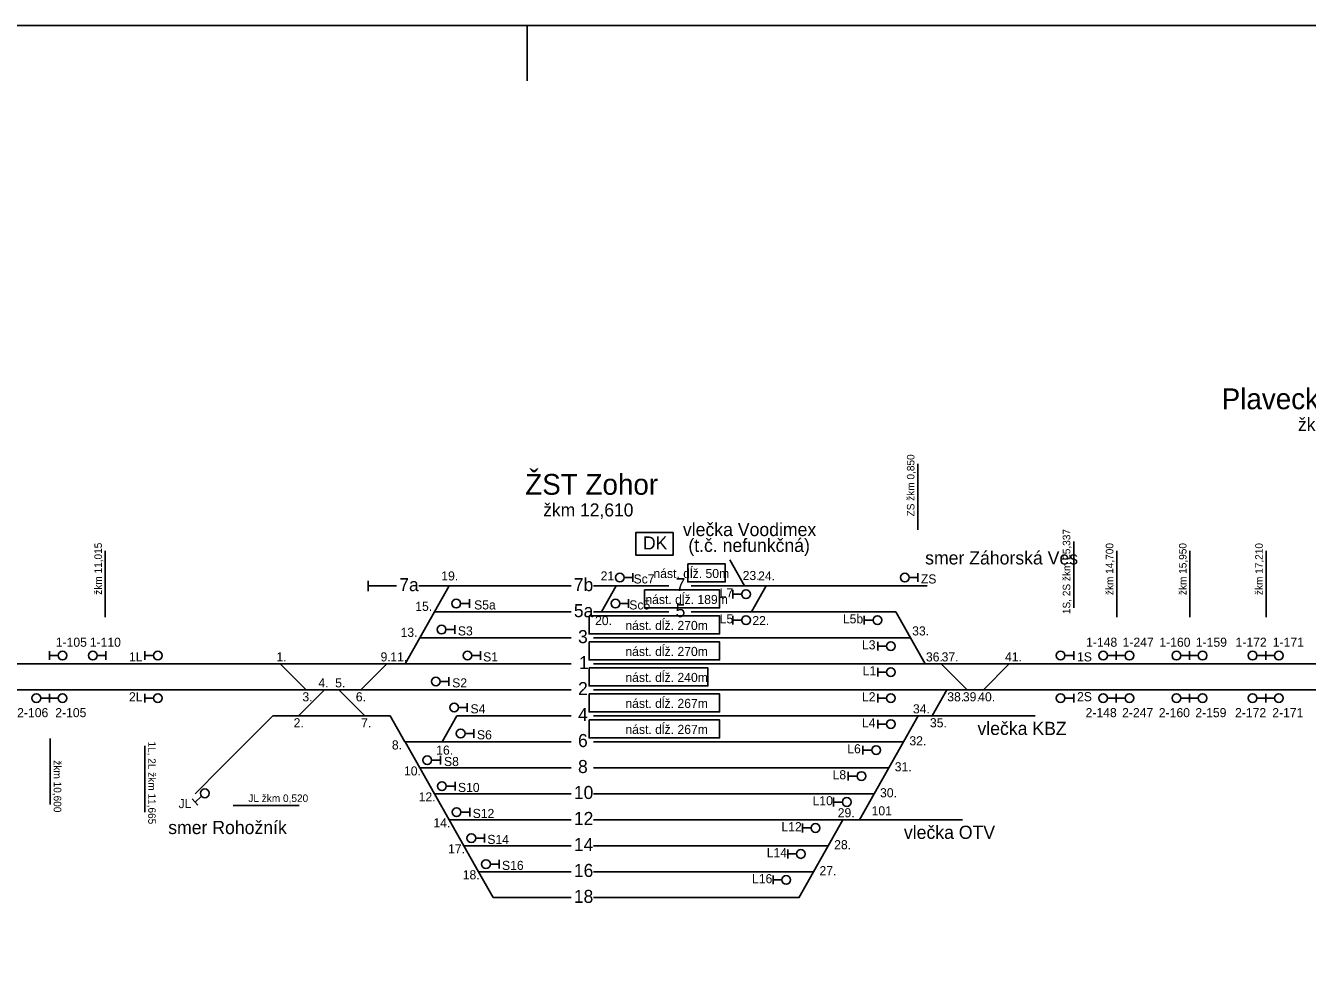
# Model space of a CAD drawing. Extents: x -119 to 851, y -238 to 59.
# Drawn here: x 52.5 to 151.1, y -14.4 to 59 of the extents above; entities that cross this region are included whole.
import ezdxf

# ---------------------------------------------------------------- set-up
doc = ezdxf.new("R2010")
doc.units = 0
for name, color, linetype in [('budova', 7, 'Continuous'), ('Level 2', 7, 'Continuous'), ('nastupistia', 7, 'Continuous'), ('netlač', 7, 'Continuous'), ('popisky navestidla', 7, 'Continuous'), ('popisky stanic a zastavok', 7, 'Continuous'), ('PU_navestidla', 7, 'Continuous'), ('PU_oznacenie navestidiel', 7, 'Continuous'), ('PU_stan_kolaje', 7, 'Continuous'), ('PU_vlecky', 7, 'Continuous')]:
    doc.layers.add(name, color=color, linetype=linetype)

msp = doc.modelspace()

# ---------------------------------------------------------------- linework, layer by layer
at = {"layer": 'budova'}
msp.add_lwpolyline([(102.283, 19.997), (99.416, 19.997), (99.416, 18.249), (102.283, 18.249)], close=True, dxfattribs=at)
at = {"layer": 'Level 2'}
for p, q in [((78.82, 16.285), (78.82, 15.485)), ((64.994, 9.889), (61.622, 9.889)), ((83.291, 9.889), (64.994, 9.889)), ((94.434, 9.889), (83.291, 9.889)), ((109.088, 9.889), (96.158, 9.889)), ((133.114, 9.889), (109.088, 9.889)), ((84.291, 7.89), (61.622, 7.89)), ((94.434, 7.89), (84.291, 7.89)), ((107.888, 7.89), (96.158, 7.89)), ((124.086, 7.89), (107.888, 7.89)), ((133.114, 7.89), (124.086, 7.89))]:
    msp.add_line(p, q, dxfattribs=at)
at = {"layer": 'nastupistia'}
for points in [[(103.408, 17.573), (106.293, 17.573), (106.293, 16.188), (103.408, 16.188)], [(100.081, 15.574), (105.856, 15.574), (105.856, 14.189), (100.081, 14.189)], [(95.817, 13.575), (105.856, 13.575), (105.856, 12.19), (95.817, 12.19)], [(95.817, 11.576), (105.856, 11.576), (105.856, 10.191), (95.817, 10.191)], [(95.817, 9.577), (104.958, 9.577), (104.958, 8.192), (95.817, 8.192)], [(95.817, 7.578), (105.856, 7.578), (105.856, 6.193), (95.817, 6.193)], [(95.817, 5.579), (105.856, 5.579), (105.856, 4.194), (95.817, 4.194)]]:
    msp.add_lwpolyline(points, close=True, dxfattribs=at)
at = {"layer": 'netlač'}
for p, q in [((80.999, 15.886), (78.82, 15.885)), ((85.049, 15.886), (82.722, 15.886)), ((94.434, 15.886), (85.049, 15.886)), ((96.158, 15.886), (97.91, 15.886)), ((97.91, 15.886), (100.695, 15.886)), ((100.695, 15.886), (101.945, 15.886)), ((103.669, 15.886), (109.436, 15.886)), ((109.436, 15.886), (121.834, 15.886)), ((94.434, 13.887), (83.918, 13.887)), ((96.158, 13.887), (101.945, 13.887)), ((103.669, 13.887), (119.418, 13.887)), ((94.434, 11.888), (82.788, 11.888)), ((96.158, 11.888), (120.548, 11.888)), ((12.578, 9.889), (61.622, 9.889)), ((133.114, 9.889), (179.871, 9.889)), ((12.578, 7.89), (61.622, 7.89)), ((133.114, 7.89), (179.871, 7.89)), ((80.5, 5.891), (71.486, 5.891)), ((85.642, 5.891), (94.434, 5.891)), ((122.208, 5.891), (96.158, 5.891)), ((122.208, 5.891), (130.153, 5.891)), ((81.63, 3.892), (94.434, 3.892)), ((96.158, 3.892), (120.01, 3.892)), ((82.785, 1.893), (94.434, 1.893)), ((96.158, 1.893), (118.88, 1.893)), ((83.915, -0.105), (94.434, -0.105)), ((96.158, -0.105), (117.75, -0.105)), ((85.045, -2.104), (94.434, -2.104)), ((96.158, -2.104), (116.62, -2.104)), ((116.62, -2.104), (124.565, -2.104)), ((86.175, -4.102), (94.434, -4.102)), ((96.158, -4.102), (114.222, -4.102)), ((87.305, -6.101), (94.434, -6.101)), ((96.158, -6.101), (113.092, -6.101)), ((88.435, -8.099), (94.434, -8.099)), ((96.158, -8.099), (111.962, -8.099))]:
    msp.add_line(p, q, dxfattribs=at)
at = {"layer": 'popisky navestidla'}
for p, q in [((91.049, 58.992), (91.049, 54.755)), ((121.119, 20.199), (121.119, 25.29)), ((133.114, 14.202), (133.114, 19.293)), ((58.586, 13.488), (58.586, 18.579)), ((136.424, 13.488), (136.424, 18.579)), ((142.059, 13.488), (142.059, 18.579)), ((147.924, 13.488), (147.924, 18.579)), ((54.352, 4.154), (54.352, -0.937)), ((61.622, 3.578), (61.622, -1.513)), ((68.417, -1.003), (73.508, -1.003))]:
    msp.add_line(p, q, dxfattribs=at)
msp.add_lwpolyline([(-118.951, -238.008), (851.049, -238.008), (851.049, 58.992), (-118.951, 58.992)], close=True, dxfattribs=at)
at = {"layer": 'PU_navestidla'}
for p, q in [((99.188, 16.859), (99.188, 16.187)), ((121.119, 16.859), (121.119, 16.187)), ((99.188, 16.522), (98.516, 16.522)), ((121.119, 16.522), (120.447, 16.522)), ((86.603, 14.86), (86.603, 14.188)), ((98.86, 14.86), (98.86, 14.188)), ((106.887, 14.914), (106.887, 15.586)), ((106.887, 15.251), (107.559, 15.251)), ((86.603, 14.523), (85.931, 14.523)), ((98.86, 14.523), (98.188, 14.523)), ((85.473, 12.861), (85.473, 12.189)), ((106.887, 12.915), (106.887, 13.587)), ((106.887, 13.252), (107.559, 13.252)), ((116.997, 12.915), (116.997, 13.587)), ((116.997, 13.252), (117.669, 13.252)), ((85.473, 12.524), (84.801, 12.524)), ((54.286, 10.86), (54.286, 10.188)), ((58.627, 10.185), (58.627, 10.857)), ((61.622, 10.861), (61.622, 10.189)), ((87.471, 10.862), (87.471, 10.19)), ((118.028, 10.916), (118.028, 11.588)), ((118.028, 11.253), (118.7, 11.253)), ((133.114, 10.862), (133.114, 10.19)), ((136.391, 10.86), (136.391, 10.188)), ((136.391, 10.86), (136.391, 10.188)), ((142.025, 10.86), (142.025, 10.188)), ((142.025, 10.86), (142.025, 10.188)), ((147.89, 10.86), (147.89, 10.188)), ((147.89, 10.86), (147.89, 10.188)), ((54.286, 10.522), (54.958, 10.522)), ((58.627, 10.522), (57.955, 10.522)), ((61.622, 10.523), (62.294, 10.523)), ((87.471, 10.525), (86.799, 10.525)), ((133.114, 10.525), (132.442, 10.525)), ((136.391, 10.522), (135.719, 10.522)), ((136.391, 10.522), (137.063, 10.522)), ((142.025, 10.522), (141.353, 10.522)), ((142.025, 10.522), (142.697, 10.522)), ((147.89, 10.522), (147.218, 10.522)), ((147.89, 10.522), (148.562, 10.522)), ((118.028, 8.917), (118.028, 9.589)), ((118.028, 9.254), (118.7, 9.254)), ((85.034, 8.526), (84.362, 8.526)), ((85.034, 8.863), (85.034, 8.191)), ((54.286, 7.251), (53.614, 7.251)), ((54.286, 6.917), (54.286, 7.589)), ((54.286, 7.589), (54.286, 6.917)), ((54.286, 7.254), (54.958, 7.254)), ((61.622, 6.918), (61.622, 7.59)), ((61.622, 7.255), (62.294, 7.255)), ((118.028, 6.918), (118.028, 7.59)), ((118.028, 7.255), (118.7, 7.255)), ((133.114, 7.255), (132.442, 7.255)), ((133.114, 6.918), (133.114, 7.59)), ((136.391, 7.254), (135.719, 7.254)), ((136.391, 6.917), (136.391, 7.589)), ((136.391, 6.917), (136.391, 7.589)), ((136.391, 7.254), (137.063, 7.254)), ((142.025, 7.254), (141.353, 7.254)), ((142.025, 6.917), (142.025, 7.589)), ((142.025, 6.917), (142.025, 7.589)), ((142.025, 7.254), (142.697, 7.254)), ((147.89, 7.254), (147.218, 7.254)), ((147.89, 6.917), (147.89, 7.589)), ((147.89, 6.917), (147.89, 7.589)), ((147.89, 7.254), (148.562, 7.254)), ((86.446, 6.527), (85.774, 6.527)), ((86.446, 6.864), (86.446, 6.192)), ((118.028, 4.919), (118.028, 5.591)), ((118.028, 5.256), (118.7, 5.256)), ((86.942, 4.528), (86.27, 4.528)), ((86.942, 4.865), (86.942, 4.193)), ((116.897, 2.92), (116.897, 3.592)), ((116.897, 3.257), (117.569, 3.257)), ((84.371, 2.474), (83.699, 2.474)), ((84.371, 2.811), (84.371, 2.139)), ((115.767, 0.921), (115.767, 1.593)), ((115.767, 1.258), (116.439, 1.258)), ((85.501, 0.475), (84.829, 0.475)), ((85.501, 0.812), (85.501, 0.141)), ((65.714, -0.993), (65.267, -0.491)), ((65.489, -0.741), (65.991, -0.294)), ((114.637, -1.078), (114.637, -0.406)), ((114.637, -0.741), (115.309, -0.741)), ((86.631, -1.523), (85.959, -1.523)), ((86.631, -1.186), (86.631, -1.858)), ((112.238, -3.077), (112.238, -2.405)), ((112.238, -2.74), (112.91, -2.74)), ((87.761, -3.522), (87.089, -3.522)), ((87.761, -3.184), (87.761, -3.856)), ((111.108, -5.075), (111.108, -4.403)), ((111.108, -4.738), (111.78, -4.738)), ((88.891, -5.52), (88.219, -5.52)), ((88.891, -5.183), (88.891, -5.855)), ((109.978, -7.075), (109.978, -6.403)), ((109.978, -6.738), (110.65, -6.738))]:
    msp.add_line(p, q, dxfattribs=at)
for centre in [(98.18, 16.523), (120.111, 16.523), (85.595, 14.524), (97.852, 14.524), (107.895, 15.25), (84.465, 12.525), (107.895, 13.251), (118.005, 13.251), (55.294, 10.524), (57.619, 10.521), (62.63, 10.525), (86.463, 10.526), (119.036, 11.252), (132.106, 10.526), (135.383, 10.524), (137.399, 10.524), (141.017, 10.524), (143.033, 10.524), (146.882, 10.524), (148.898, 10.524), (119.036, 9.253), (84.026, 8.527), (53.278, 7.253), (55.294, 7.253), (62.63, 7.254), (119.036, 7.254), (132.106, 7.254), (135.383, 7.253), (137.399, 7.253), (141.017, 7.253), (143.033, 7.253), (146.882, 7.253), (148.898, 7.253), (85.438, 6.528), (119.036, 5.255), (85.934, 4.529), (117.905, 3.256), (83.363, 2.475), (116.775, 1.257), (66.243, -0.072), (84.493, 0.477), (115.645, -0.742), (85.623, -1.522), (113.246, -2.741), (86.753, -3.52), (112.116, -4.739), (87.883, -5.519), (110.986, -6.739)]:
    msp.add_circle(centre, 0.336, dxfattribs=at)
at = {"layer": 'PU_stan_kolaje'}
for points in [[(107.766, 15.886), (106.637, 17.884)], [(85.049, 15.886), (83.918, 13.887)], [(97.91, 15.886), (96.779, 13.887)], [(109.436, 15.886), (108.305, 13.887)], [(83.918, 13.887), (82.788, 11.888)], [(120.548, 11.888), (119.418, 13.887)], [(82.788, 11.888), (81.658, 9.889)], [(121.678, 9.889), (120.548, 11.888)], [(74.042, 7.89), (72.043, 9.889)], [(78.247, 7.89), (80.246, 9.889)], [(124.916, 7.89), (122.917, 9.889)], [(126.16, 7.89), (128.159, 9.889)], [(73.461, 5.891), (75.46, 7.89)], [(78.564, 5.891), (76.565, 7.89)], [(123.339, 7.89), (122.208, 5.891)], [(69.487, 3.892), (71.486, 5.891)], [(81.63, 3.892), (80.5, 5.89)], [(85.642, 5.891), (84.512, 3.892)], [(121.14, 5.891), (120.01, 3.892)], [(67.488, 1.893), (69.487, 3.892)], [(82.785, 1.893), (81.655, 3.892)], [(120.01, 3.892), (118.88, 1.893)], [(65.489, -0.106), (67.488, 1.893)], [(83.915, -0.105), (82.785, 1.893)], [(118.88, 1.893), (117.749, -0.106)], [(85.045, -2.104), (83.915, -0.105)], [(117.749, -0.106), (116.619, -2.105)], [(86.175, -4.102), (85.045, -2.104)], [(115.352, -2.104), (114.221, -4.103)], [(87.305, -6.101), (86.175, -4.102)], [(114.221, -4.103), (113.091, -6.102)], [(88.435, -8.099), (87.305, -6.101)], [(113.091, -6.102), (111.961, -8.101)]]:
    msp.add_lwpolyline(points, dxfattribs=at)

# ---------------------------------------------------------------- texts
at = {"layer": 'budova'}
msp.add_text('DK', height=1.0044, dxfattribs=at).set_placement((99.971, 18.688))
at = {"layer": 'nastupistia'}
for s, p in [('nást. dĺž. 50m', (100.771, 16.49)), ('nást. dĺž. 189m', (100.148, 14.491)), ('nást. dĺž. 270m', (98.611, 12.492)), ('nást. dĺž. 270m', (98.611, 10.493)), ('nást. dĺž. 240m', (98.611, 8.494)), ('nást. dĺž. 267m', (98.611, 6.495)), ('nást. dĺž. 267m', (98.611, 4.496))]:
    msp.add_text(s, height=0.7, dxfattribs=at).set_placement(p)
at = {"layer": 'popisky navestidla'}
for s, height, rotation, p in [('ZS žkm 0,850 ', 0.57931, 90, (120.856, 21.228)), ('1S, 2S žkm 25,337', 0.57931, 90, (132.851, 13.716)), ('žkm 11,015', 0.5793, 90, (58.323, 15.205)), ('žkm 14,700', 0.5793, 90, (136.161, 15.18)), ('žkm 15,950', 0.5793, 90, (141.796, 15.18)), ('žkm 17,210', 0.5793, 90, (147.661, 15.18)), ('1L, 2L žkm 11,665', 0.57931, 270, (61.885, 3.921)), ('žkm 10,600', 0.5793, 270, (54.615, 2.462)), ('JL žkm 0,520', 0.57931, 360, (69.592, -0.74))]:
    msp.add_text(s, height=height, rotation=rotation, dxfattribs=at).set_placement(p)
at = {"layer": 'popisky stanic a zastavok'}
for s, height, p in [('Plavecký Štvrtok zast.', 1.6, (144.502, 29.479)), ('žkm 17,993', 1.0044, (150.379, 27.811)), ('ŽST Zohor', 1.6, (90.904, 22.898)), ('žkm 12,610', 1.0044, (92.285, 21.23))]:
    msp.add_text(s, height=height, dxfattribs=at).set_placement(p)
at = {"layer": 'PU_oznacenie navestidiel'}
for s, p in [('19.', (84.445, 16.305)), ('21.', (96.706, 16.303)), ('Sc7', (99.24, 16.073)), ('23.', (107.636, 16.336)), ('24.', (108.828, 16.303)), ('ZS', (121.352, 16.073)), ('L7', (105.869, 15)), ('15.', (82.44, 13.963)), ('S5a', (86.967, 14.074)), ('Sc5', (98.91, 14.074)), ('20.', (96.277, 12.868)), ('L5', (105.866, 13.001)), ('22.', (108.382, 12.868)), ('L5b', (115.348, 13.001)), ('1-105', (54.773, 11.203)), ('1-110', (57.391, 11.203)), ('13.', (81.309, 11.964)), ('S3', (85.72, 12.075)), ('33.', (120.683, 12.074)), ('1-148', (134.068, 11.203)), ('1-247', (136.879, 11.203)), ('1-160', (139.705, 11.203)), ('1-159', (142.513, 11.203)), ('1-172', (145.571, 11.203)), ('1-171', (148.434, 11.203)), ('L3', (116.818, 11.002)), ('1L', (60.409, 10.075)), ('1.', (71.754, 10.075)), ('9.', (79.77, 10.075)), ('11.', (80.516, 10.075)), ('S1', (87.663, 10.076)), ('36.', (121.743, 10.075)), ('37.', (122.949, 10.075)), ('41.', (127.822, 10.075)), ('1S', (133.37, 10.076)), ('L1', (116.873, 9.003)), ('4.', (74.983, 8.076)), ('5.', (76.276, 8.076)), ('S2', (85.283, 8.077)), ('2L', (60.409, 7.004)), ('3.', (73.753, 7.004)), ('6.', (77.864, 7.004)), ('L2', (116.82, 7.004)), ('38.', (123.385, 7.004)), ('39.', (124.583, 7.004)), ('40.', (125.765, 7.004)), ('2S', (133.37, 7.015)), ('2-106', (51.802, 5.786)), ('2-105', (54.734, 5.786)), ('S4', (86.693, 6.078)), ('34.', (120.742, 6.077)), ('2-148', (134.03, 5.786)), ('2-247', (136.841, 5.786)), ('2-160', (139.666, 5.786)), ('2-159', (142.474, 5.786)), ('2-172', (145.532, 5.786)), ('2-171', (148.395, 5.786)), ('2.', (73.078, 5.005)), ('7.', (78.275, 5.005)), ('L4', (116.819, 5.005)), ('35.', (122.05, 5.005)), ('8.', (80.641, 3.3)), ('S6', (87.189, 4.079)), ('32.', (120.469, 3.618)), ('16.', (84.052, 2.902)), ('L6', (115.688, 3.006)), ('10.', (81.573, 1.302)), ('S8', (84.651, 2.025)), ('31.', (119.339, 1.619)), ('L8', (114.557, 1.007)), ('12.', (82.703, -0.697)), ('S10', (85.726, 0.027)), ('30.', (118.209, -0.38)), ('JL', (64.221, -1.212)), ('L10', (113.016, -0.992)), ('S12', (86.858, -1.972)), ('29.', (114.953, -1.918)), ('101', (117.56, -1.768)), ('14.', (83.833, -2.695)), ('L12', (110.62, -2.991)), ('S14', (87.986, -3.97)), ('28.', (114.68, -4.377)), ('17.', (84.963, -4.694)), ('L14', (109.488, -4.989)), ('S16', (89.115, -5.969)), ('27.', (113.55, -6.376)), ('18.', (86.093, -6.692)), ('L16', (108.357, -6.989))]:
    msp.add_text(s, height=0.7, dxfattribs=at).set_placement(p)
at = {"layer": 'PU_stan_kolaje'}
for s, height, p in [('7a', 1.0044, (81.209, 15.481)), ('7b', 1.0044, (94.644, 15.481)), ('7', 1.004, (102.478, 15.481)), ('5a', 1.0044, (94.645, 13.482)), ('5', 1.004, (102.474, 13.482)), ('3', 1.004, (94.967, 11.483)), ('1', 1.004, (95.046, 9.484)), ('2', 1.004, (94.97, 7.485)), ('4', 1.004, (94.968, 5.486)), ('6', 1.004, (94.967, 3.487)), ('8', 1.004, (94.966, 1.488)), ('10', 1.0044, (94.648, -0.51)), ('12', 1.0044, (94.651, -2.509)), ('14', 1.0044, (94.648, -4.507)), ('16', 1.0044, (94.647, -6.506)), ('18', 1.0044, (94.646, -8.504))]:
    msp.add_text(s, height=height, dxfattribs=at).set_placement(p)
at = {"layer": 'PU_vlecky'}
for s, p in [('vlečka Voodimex', (103.039, 19.718)), ('(t.č. nefunkčná)', (103.457, 18.5)), ('smer Záhorská Ves', (121.681, 17.535)), ('vlečka KBZ', (125.709, 4.416)), ('smer Rohožník', (63.427, -3.208)), ('vlečka OTV', (120.047, -3.578))]:
    msp.add_text(s, height=1.015, dxfattribs=at).set_placement(p)

doc.saveas('drawing.dxf')
